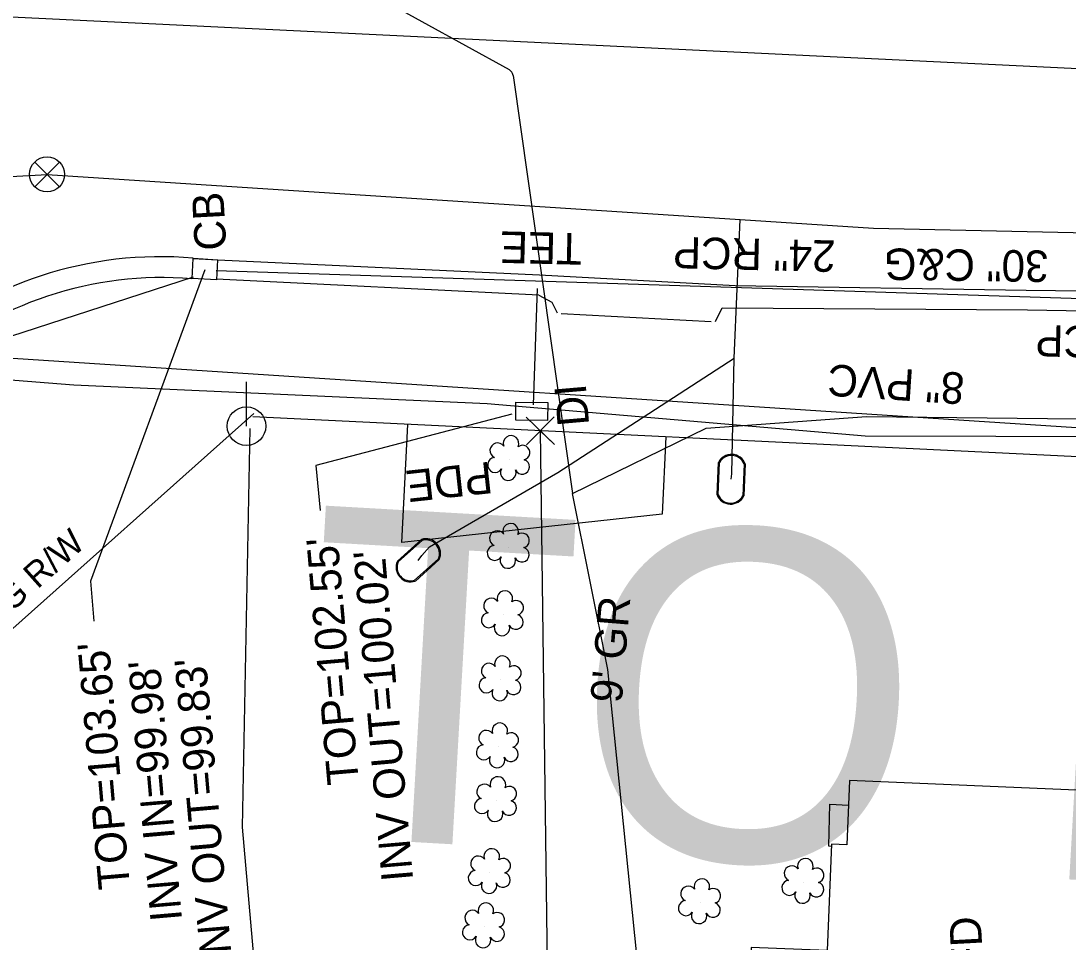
# Model space of a CAD drawing. Extents: x 2364404 to 2371833, y 798876 to 809754.
# Drawn here: x 2369024.2 to 2369157.2, y 801211 to 801327.9 of the extents above; entities that cross this region are included whole.
import ezdxf

# ---------------------------------------------------------------- set-up
doc = ezdxf.new("R2010")
doc.units = 0
for name, color, linetype in [('Exist Building', 7, 'Continuous'), ('Exist Building Text', 7, 'Continuous'), ('Exist Other Culture Area Outline', 7, 'Continuous'), ('Exist Property Corner CELL', 7, 'Continuous'), ('Exist Property Line', 7, 'Continuous'), ('Exist Property Line PSD', 7, 'Continuous'), ('Exist Right of Way Easement Line', 7, 'Continuous'), ('Exist Right of Way Easement Line Text', 7, 'Continuous'), ('Exist Right of Way Line', 7, 'Continuous'), ('Exist Right of Way Line Text', 7, 'Continuous'), ('Exist Roads Curbs', 7, 'Continuous'), ('Exist Roads Curbs Text', 7, 'Continuous'), ('Exist Roads EOP', 7, 'Continuous'), ('Exist Roads EOP Other', 7, 'Continuous'), ('Exist Roads Soil Text', 7, 'Continuous'), ('Exist Structure Minor Catch Basin', 7, 'Continuous'), ('Exist Structure Minor Catch Basin Leader', 7, 'Continuous'), ('Exist Structure Minor Catch Basin Text', 7, 'Continuous'), ('Exist Structure Minor Catch Basin Top Elevation', 7, 'Continuous'), ('Exist Structure Minor Drop Inlet', 7, 'Continuous'), ('Exist Structure Minor Drop Inlet Leader', 7, 'Continuous'), ('Exist Structure Minor Drop Inlet Text', 7, 'Continuous'), ('Exist Structure Minor Drop Inlet Top Elevation', 7, 'Continuous'), ('Exist Structure Minor Pipes RCP 15 Inch Text', 7, 'Continuous'), ('Exist Structure Minor Pipes RCP 18 Inch', 7, 'Continuous'), ('Exist Structure Minor Pipes RCP 18 Inch Invert', 7, 'Continuous'), ('Exist Structure Minor Pipes RCP 24 Inch', 7, 'Continuous'), ('Exist Structure Minor Pipes RCP 24 Inch Invert', 7, 'Continuous'), ('Exist Structure Minor Pipes RCP 24 Inch Text', 7, 'Continuous'), ('Exist Utilities Gas UG Line SUE LOS B', 7, 'Continuous'), ('Exist Utilities Gas UG Line SUE LOS D', 7, 'Continuous'), ('Exist Utilities Power Pole CELL', 7, 'Continuous'), ('Exist Utilities Power UG Cable SUE LOS B', 7, 'Continuous'), ('Exist Utilities Sanitary Sewer UG Line', 7, 'Continuous'), ('Exist Utilities Sanitary Sewer UG Line Text', 7, 'Continuous'), ('Exist Utilities Telephone UG FO SUE LOS B', 7, 'Continuous'), ('Exist Utilities Water Meter CELL', 7, 'Continuous'), ('Exist Utilities Water UG Line SUE LOS B', 7, 'Continuous'), ('Exist Utilities Water Valve CELL', 7, 'Continuous'), ('Exist Vegetation Shrub CELL', 7, 'Continuous'), ('Prop Horizontal Alignment', 7, 'Continuous')]:
    doc.layers.add(name, color=color, linetype=linetype)

msp = doc.modelspace()

# ---------------------------------------------------------------- linework, layer by layer
at = {"layer": 'Exist Building'}
msp.add_lwpolyline([(2369116.05, 801188.54), (2369154.1, 801186.92), (2369153.68, 801176.96), (2369171.91, 801176.18), (2369173.74, 801219.03), (2369160.96, 801219.57), (2369161.03, 801221.25), (2369158.88, 801221.35), (2369159.25, 801230.23), (2369129.46, 801231.5), (2369129.11, 801223.34), (2369127.18, 801223.42), (2369126.61, 801209.92), (2369116.98, 801210.33)], close=True, dxfattribs=at)
at = {"layer": 'Exist Other Culture Area Outline'}
msp.add_lwpolyline([(2369127.17, 801223.15), (2369126.84, 801223.17), (2369126.97, 801228.5), (2369129.33, 801228.38)], dxfattribs=at)
at = {"layer": 'Exist Property Corner CELL'}
msp.add_line((2369090.2, 801275.9), (2369090.2, 801275.9), dxfattribs=at)
msp.add_lwpolyline([(2369088.41, 801277.65), (2369091.99, 801274.16), (2369090.2, 801275.9), (2369091.94, 801277.69), (2369088.45, 801274.11)], dxfattribs=at)
at = {"layer": 'Exist Property Line'}
msp.add_line((2369090.2, 801275.9), (2369092.57, 801086.03), dxfattribs=at)
at = {"layer": 'Exist Right of Way Easement Line'}
for p, q in [((2369072.63, 801261.73), (2369073.36, 801276.72)), ((2369106.13, 801275.13), (2369105.66, 801265.34)), ((2369105.66, 801265.34), (2369072.63, 801261.73))]:
    msp.add_line(p, q, dxfattribs=at)
at = {"layer": 'Exist Right of Way Line'}
for p, q in [((2369000.5, 801230.53), (2369053.81, 801278.12)), ((2369391.23, 801261.31), (2369053.69, 801277.67))]:
    msp.add_line(p, q, dxfattribs=at)
at = {"layer": 'Exist Roads Curbs'}
msp.add_line((2369090, 801293.14), (2369049.1, 801295.15), dxfattribs=at)
for points in [[(2369090, 801293.14), (2369091.66, 801292.25), (2369092.32, 801290.9)], [(2369112.45, 801289.8), (2369113.28, 801291.5), (2369152.08, 801291.27), (2369174.17, 801290.88)]]:
    msp.add_lwpolyline(points, dxfattribs=at)
msp.add_arc((2369042.24, 801248.99), 46.37, 85.433, 177.1394, dxfattribs=at)
at = {"layer": 'Exist Roads EOP'}
msp.add_lwpolyline([(2369046.12, 801297.83), (2369049.27, 801297.59), (2369090.09, 801295.72), (2369114.94, 801294.33), (2369151.87, 801293.75), (2369174.26, 801293.5), (2369177.42, 801293.29), (2369182.46, 801293.26)], dxfattribs=at)
msp.add_arc((2369041.99, 801249.29), 48.72, 85.1304, 177.211, dxfattribs=at)
at = {"layer": 'Exist Roads EOP Other'}
msp.add_line((2369092.84, 801290.81), (2369111.91, 801289.8), dxfattribs=at)
at = {"layer": 'Exist Structure Minor Catch Basin'}
msp.add_lwpolyline([(2369049.07, 801295.08), (2369045.98, 801295.26), (2369046.13, 801297.78), (2369049.22, 801297.59)], close=True, dxfattribs=at)
at = {"layer": 'Exist Structure Minor Catch Basin Leader'}
msp.add_lwpolyline([(2369047.59, 801296.35), (2369033.07, 801256.82), (2369033.51, 801251.73)], dxfattribs=at)
at = {"layer": 'Exist Structure Minor Drop Inlet'}
msp.add_lwpolyline([(2369091.12, 801277.2), (2369087.08, 801277.24), (2369087.11, 801279.52), (2369091.14, 801279.48)], close=True, dxfattribs=at)
at = {"layer": 'Exist Structure Minor Drop Inlet Leader'}
msp.add_lwpolyline([(2369086.57, 801278), (2369061.7, 801271.49), (2369062.23, 801265.77)], dxfattribs=at)
at = {"layer": 'Exist Structure Minor Pipes RCP 18 Inch'}
msp.add_line((2369089.78, 801293.95), (2369089.3, 801279.19), dxfattribs=at)
at = {"layer": 'Exist Structure Minor Pipes RCP 24 Inch'}
for p, q in [((2368933.97, 801258.92), (2369046.17, 801295.47)), ((2369049.02, 801296.27), (2369174.37, 801292.21))]:
    msp.add_line(p, q, dxfattribs=at)
at = {"layer": 'Exist Utilities Gas UG Line SUE LOS B'}
msp.add_lwpolyline([(2369118.86, 801188.27), (2369117.59, 801188.36), (2369110.54, 801188.9), (2369103.63, 801197.65), (2369098.75, 801245.61), (2369094.3, 801267.96), (2369111.25, 801276.24), (2369131.6, 801277.73), (2369181.39, 801277.17), (2369233.34, 801275.38), (2369282.3, 801275.27), (2369332.01, 801277.6), (2369390.07, 801279.86), (2369395.82, 801275.43), (2369398.6, 801270.1), (2369399.44, 801261.78), (2369396.89, 801225.39), (2369398.43, 801189.72), (2369405.11, 801186.6), (2369411.08, 801188.31)], dxfattribs=at)
at = {"layer": 'Exist Utilities Gas UG Line SUE LOS D'}
for p, q in [((2369059.99, 801336.23), (2369086.23, 801321.76)), ((2369086.74, 801321.03), (2369094.3, 801267.96))]:
    msp.add_line(p, q, dxfattribs=at)
msp.add_arc((2369085.75, 801320.88), 1, 8.1108, 61.128, dxfattribs=at)
at = {"layer": 'Exist Utilities Power Pole CELL'}
for q in [(2369052.89, 801282.13), (2369052.89, 801276.5)]:
    msp.add_line((2369052.89, 801276.5), q, dxfattribs=at)
msp.add_circle((2369052.89, 801276.5), 2.45, dxfattribs=at)
at = {"layer": 'Exist Utilities Power UG Cable SUE LOS B'}
msp.add_lwpolyline([(2369047.98, 801185.6), (2369049.75, 801185.77), (2369052.98, 801186.83), (2369054.61, 801188.29), (2369055.44, 801190.87), (2369052.38, 801225.59), (2369053.36, 801276.19)], dxfattribs=at)
at = {"layer": 'Exist Utilities Sanitary Sewer UG Line'}
msp.add_line((2369003.67, 801286.39), (2369342.03, 801264.33), dxfattribs=at)
at = {"layer": 'Exist Utilities Telephone UG FO SUE LOS B'}
msp.add_lwpolyline([(2368438.53, 801311.53), (2368477.91, 801308.41), (2368528.46, 801305.56), (2368579.31, 801304.77), (2368628.94, 801301.83), (2368679.36, 801299.84), (2368779.99, 801301.63), (2368829.13, 801300.67), (2368829.59, 801300.57), (2368980.58, 801285.7), (2369030.97, 801281.74), (2369083.47, 801279.38), (2369131.43, 801275.25), (2369181.24, 801275.14), (2369233.3, 801274.22), (2369282.24, 801272.78), (2369328.85, 801272.19), (2369330.73, 801272.71)], dxfattribs=at)
at = {"layer": 'Exist Utilities Water Meter CELL'}
for p, q in [((2369114.43, 801269.76), (2369114.43, 801269.76)), ((2369074.7, 801259.46), (2369074.7, 801259.46))]:
    msp.add_line(p, q, dxfattribs=at)
for points in [[(2369112.64, 801267.79), (2369112.81, 801271.89)], [(2369112.78, 801267.78), (2369112.95, 801271.88)], [(2369116.07, 801271.73), (2369115.9, 801267.66)], [(2369116.21, 801271.72), (2369116.04, 801267.65)], [(2369072.05, 801259.36), (2369075.1, 801262.1)], [(2369072.15, 801259.26), (2369075.19, 801262)], [(2369077.26, 801259.66), (2369074.23, 801256.94)], [(2369077.36, 801259.56), (2369074.33, 801256.83)]]:
    msp.add_lwpolyline(points, dxfattribs=at)
for centre, radius, start, end in [((2369114.47, 801271.06), 1.86, 20.8408, 153.6422), ((2369114.47, 801271.05), 1.73, 22.9637, 151.4451), ((2369114.37, 801268.46), 1.86, 201.3111, 333.9711), ((2369114.37, 801268.45), 1.73, 202.7899, 332.5356), ((2369075.67, 801260.34), 1.86, 335.1279, 107.9293), ((2369075.66, 801260.33), 1.73, 337.2508, 105.7322), ((2369073.74, 801258.59), 1.86, 155.5982, 288.2582), ((2369073.73, 801258.59), 1.73, 157.077, 286.8227)]:
    msp.add_arc(centre, radius, start, end, dxfattribs=at)
at = {"layer": 'Exist Utilities Water UG Line SUE LOS B'}
for points in [[(2369012.89, 801307.63), (2369027.57, 801308.45), (2369115.59, 801302.73), (2369132.52, 801301.62), (2369177.38, 801300.64), (2369244.93, 801298.66), (2369282.1, 801297.43), (2369331.66, 801295.61), (2369383.14, 801292.84), (2369433.44, 801289.64), (2369445.05, 801289.69), (2369474.51, 801289.35)], [(2369114.43, 801269.76), (2369114.53, 801270.46), (2369114.8, 801285.14), (2369115.59, 801302.73)], [(2369074.7, 801259.46), (2369075.15, 801260.08), (2369076.12, 801261.19), (2369092.44, 801270.63), (2369114.8, 801285.14)]]:
    msp.add_lwpolyline(points, dxfattribs=at)
at = {"layer": 'Exist Utilities Water Valve CELL'}
msp.add_lwpolyline([(2369029.15, 801310.02), (2369026, 801306.87), (2369027.57, 801308.45), (2369029.15, 801306.87), (2369026, 801310.02)], dxfattribs=at)
msp.add_circle((2369027.57, 801308.45), 2.23, dxfattribs=at)
at = {"layer": 'Exist Vegetation Shrub CELL'}
for p, q in [((2369086.26, 801272.27), (2369086.26, 801272.27)), ((2369086.21, 801261.11), (2369086.21, 801261.11)), ((2369085.46, 801252.57), (2369085.46, 801252.57)), ((2369085.16, 801244.29), (2369085.16, 801244.29)), ((2369084.83, 801235.79), (2369084.83, 801235.79)), ((2369084.59, 801228.97), (2369084.59, 801228.97)), ((2369083.8, 801219.83), (2369083.8, 801219.83)), ((2369123.62, 801218.6), (2369123.62, 801218.6)), ((2369110.49, 801216.01), (2369110.49, 801216.01)), ((2369083.06, 801212.95), (2369083.06, 801212.95))]:
    msp.add_line(p, q, dxfattribs=at)
for centre, radius, start, end in [((2369084.77, 801273.4), 0.968, 35.8908, 245.4216), ((2369086.48, 801274.31), 0.99, 334.8391, 200.4717), ((2369087.93, 801273.14), 0.929, 284.4567, 126.0861), ((2369084.46, 801271.57), 0.955, 95.1099, 327.9534), ((2369087.89, 801271.34), 0.937, 204.9913, 73.4601), ((2369086.13, 801270.59), 0.984, 151.2797, 21.387), ((2369086.43, 801263.15), 0.99, 334.8391, 200.4717), ((2369084.72, 801262.24), 0.968, 35.8908, 245.4216), ((2369087.88, 801261.98), 0.929, 284.4567, 126.0861), ((2369084.41, 801260.41), 0.955, 95.1099, 327.9534), ((2369087.84, 801260.18), 0.937, 204.9913, 73.4601), ((2369086.08, 801259.43), 0.984, 151.2797, 21.387), ((2369085.69, 801254.61), 0.99, 334.8391, 200.4717), ((2369083.98, 801253.69), 0.968, 35.8908, 245.4216), ((2369087.13, 801253.44), 0.929, 284.4567, 126.0861), ((2369083.66, 801251.86), 0.955, 95.1099, 327.9534), ((2369087.1, 801251.64), 0.937, 204.9913, 73.4601), ((2369085.33, 801250.88), 0.984, 151.2797, 21.387), ((2369083.68, 801245.42), 0.968, 35.8908, 245.4216), ((2369085.39, 801246.33), 0.99, 334.8391, 200.4717), ((2369086.84, 801245.16), 0.929, 284.4567, 126.0861), ((2369083.36, 801243.59), 0.955, 95.1099, 327.9534), ((2369086.8, 801243.36), 0.937, 204.9913, 73.4601), ((2369085.04, 801242.61), 0.984, 151.2797, 21.387), ((2369085.06, 801237.83), 0.99, 334.8391, 200.4717), ((2369083.34, 801236.91), 0.968, 35.8908, 245.4216), ((2369086.5, 801236.65), 0.929, 284.4567, 126.0861), ((2369083.03, 801235.08), 0.955, 95.1099, 327.9534), ((2369086.46, 801234.86), 0.937, 204.9913, 73.4601), ((2369084.7, 801234.1), 0.984, 151.2797, 21.387), ((2369084.82, 801231.01), 0.99, 334.8391, 200.4717), ((2369083.1, 801230.09), 0.968, 35.8908, 245.4216), ((2369086.26, 801229.84), 0.929, 284.4567, 126.0861), ((2369082.79, 801228.26), 0.955, 95.1099, 327.9534), ((2369086.22, 801228.04), 0.937, 204.9913, 73.4601), ((2369084.46, 801227.28), 0.984, 151.2797, 21.387), ((2369084.03, 801221.87), 0.99, 334.8391, 200.4717), ((2369082.32, 801220.96), 0.968, 35.8908, 245.4216), ((2369085.48, 801220.7), 0.929, 284.4567, 126.0861), ((2369123.85, 801220.64), 0.99, 334.8391, 200.4717), ((2369082, 801219.12), 0.955, 95.1099, 327.9534), ((2369085.44, 801218.9), 0.937, 204.9913, 73.4601), ((2369122.13, 801219.72), 0.968, 35.8908, 245.4216), ((2369125.29, 801219.47), 0.929, 284.4567, 126.0861), ((2369083.68, 801218.15), 0.984, 151.2797, 21.387), ((2369110.71, 801218.05), 0.99, 334.8391, 200.4717), ((2369121.82, 801217.89), 0.955, 95.1099, 327.9534), ((2369125.25, 801217.67), 0.937, 204.9913, 73.4601), ((2369109, 801217.14), 0.968, 35.8908, 245.4216), ((2369112.16, 801216.88), 0.929, 284.4567, 126.0861), ((2369123.49, 801216.91), 0.984, 151.2797, 21.387), ((2369083.29, 801214.99), 0.99, 334.8391, 200.4717), ((2369108.69, 801215.31), 0.955, 95.1099, 327.9534), ((2369112.12, 801215.08), 0.937, 204.9913, 73.4601), ((2369081.58, 801214.08), 0.968, 35.8908, 245.4216), ((2369084.73, 801213.82), 0.929, 284.4567, 126.0861), ((2369110.36, 801214.33), 0.984, 151.2797, 21.387), ((2369081.26, 801212.24), 0.955, 95.1099, 327.9534), ((2369082.93, 801211.27), 0.984, 151.2797, 21.387), ((2369084.7, 801212.02), 0.937, 204.9913, 73.4601)]:
    msp.add_arc(centre, radius, start, end, dxfattribs=at)
at = {"layer": 'Prop Horizontal Alignment'}
msp.add_line((2368455.83, 801355.96), (2369477.35, 801306.45), dxfattribs=at)

# ---------------------------------------------------------------- texts
at = {"layer": 'Exist Building Text'}
msp.add_text('1SFD', height=4, rotation=93.0566, dxfattribs=at).set_placement((2369146.83, 801200.71))
at = {"layer": 'Exist Property Line PSD'}
msp.add_text('TO ROCKY MOUNT', height=42, rotation=356.7396, dxfattribs=at).set_placement((2369059.32, 801224.54))
at = {"layer": 'Exist Right of Way Easement Line Text'}
msp.add_text('PDE', height=4, rotation=186.2484, dxfattribs=at).set_placement((2369083.88, 801272))
at = {"layer": 'Exist Right of Way Line Text'}
msp.add_text('EXISTING R/W', height=3.2, rotation=41.7575, dxfattribs=at).set_placement((2369010.57, 801241.66))
at = {"layer": 'Exist Roads Curbs Text'}
msp.add_text('30" C&G', height=4, rotation=179.1996, dxfattribs=at).set_placement((2369154.75, 801298.78))
at = {"layer": 'Exist Roads Soil Text'}
msp.add_text("9' GR", height=4, rotation=85.2691, dxfattribs=at).set_placement((2369100.53, 801241.27))
at = {"layer": 'Exist Structure Minor Catch Basin Text'}
msp.add_text('CB', height=4, rotation=93.0566, dxfattribs=at).set_placement((2369050.34, 801298.89))
at = {"layer": 'Exist Structure Minor Catch Basin Top Elevation'}
msp.add_text("TOP=103.65'", height=4, rotation=94.9433, dxfattribs=at).set_placement((2369038.11, 801217.86))
at = {"layer": 'Exist Structure Minor Drop Inlet Text'}
msp.add_text('DI', height=4, rotation=94.9433, dxfattribs=at).set_placement((2369096.41, 801276.66))
at = {"layer": 'Exist Structure Minor Drop Inlet Top Elevation'}
msp.add_text("TOP=102.55'", height=4, rotation=94.9433, dxfattribs=at).set_placement((2369067.17, 801231.15))
at = {"layer": 'Exist Structure Minor Pipes RCP 15 Inch Text'}
msp.add_text('15" RCP', height=4, rotation=178.597, dxfattribs=at).set_placement((2369173.74, 801288.86))
at = {"layer": 'Exist Structure Minor Pipes RCP 18 Inch Invert'}
for s, p in [("INV OUT=100.02'", (2369074.06, 801218.87)), ("INV IN=99.98'", (2369044.71, 801213.79))]:
    msp.add_text(s, height=4, rotation=94.9433, dxfattribs=at).set_placement(p)
at = {"layer": 'Exist Structure Minor Pipes RCP 24 Inch Invert'}
msp.add_text("INV OUT=99.83'", height=4, rotation=94.9433, dxfattribs=at).set_placement((2369051.09, 801208.14))
at = {"layer": 'Exist Structure Minor Pipes RCP 24 Inch Text'}
for s, p in [('TEE', (2369095.53, 801300.98)), ('24" RCP', (2369127.72, 801300.06))]:
    msp.add_text(s, height=4, rotation=178.6371, dxfattribs=at).set_placement(p)
at = {"layer": 'Exist Utilities Sanitary Sewer UG Line Text'}
msp.add_text('8" PVC', height=4, rotation=176.2683, dxfattribs=at).set_placement((2369144.15, 801283.24))

doc.saveas('drawing.dxf')
